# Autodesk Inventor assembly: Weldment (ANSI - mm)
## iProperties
Length Units: 11269
Angle Units: 11283
Time Units: 11279
Mass Units: 11290
Length Display Precision: 3
Angle Display Precision: 2
Part Number: Weldment (ANSI - mm)
Document SubType Name: Weldment
Created: 2002-06
Designer: smithga
Part Number: ex8-2
Created: 2002-11
Designer: Elise Moss
Control State: 0
Master: False
Shininess: 64.0
Angle Units: 11279
Time Units: 11290
Mass Units: 11283
Compacted: True
Density: 0.0
Volumn: 0.0
Area: 0.0
PropertySet Name: Model Information
Author: Elise Moss
